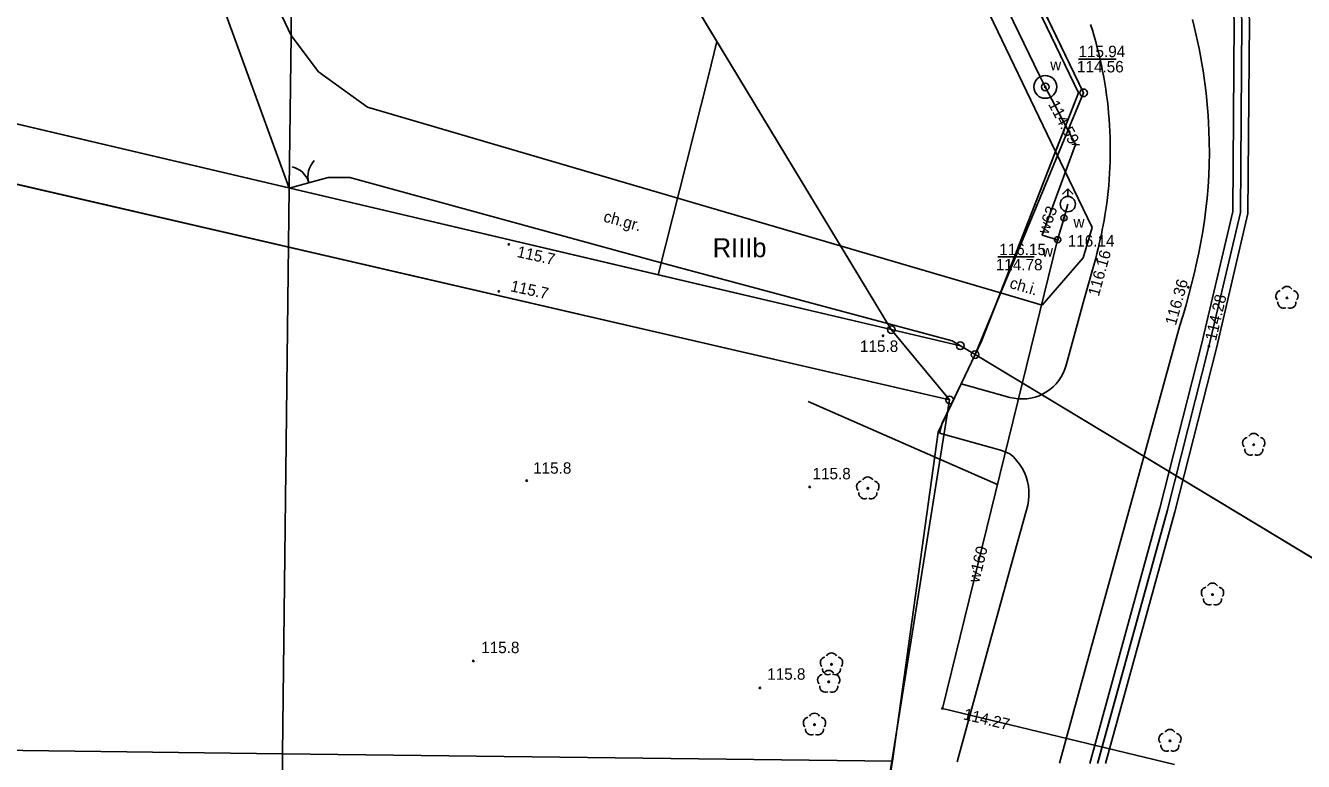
# Model space of a CAD drawing. Extents: x 6424617 to 6425697, y 5665845 to 5667190.
# Drawn here: x 6425294.6 to 6425378.5, y 5666814.1 to 5666862.4 of the extents above; entities that cross this region are included whole.
import ezdxf

# ---------------------------------------------------------------- set-up
doc = ezdxf.new("R2010")
doc.units = 0
for name, color, linetype in [('Warstwa 1', 7, 'Continuous'), ('Warstwa 10', 7, 'Continuous'), ('Warstwa 11', 7, 'Continuous'), ('Warstwa 12', 7, 'Continuous'), ('Warstwa 13', 7, 'Continuous'), ('Warstwa 14', 7, 'Continuous'), ('Warstwa 15', 7, 'Continuous'), ('Warstwa 16', 7, 'Continuous'), ('Warstwa 2', 7, 'Continuous'), ('Warstwa 20', 7, 'Continuous'), ('Warstwa 25', 7, 'Continuous'), ('Warstwa 3', 7, 'Continuous'), ('Warstwa 4', 7, 'Continuous'), ('Warstwa 5', 7, 'Continuous'), ('Warstwa 6', 7, 'Continuous'), ('Warstwa 61', 7, 'Continuous'), ('Warstwa 8', 7, 'Continuous'), ('Warstwa 9', 7, 'Continuous')]:
    doc.layers.add(name, color=color, linetype=linetype)

msp = doc.modelspace()

# ---------------------------------------------------------------- linework, layer by layer
at = {"layer": 'Warstwa 1'}
for p, q in [((6425289.177, 5666945.34), (6425340.017, 5666861.361)), ((6425289.177, 5666945.34), (6425340.017, 5666861.361)), ((6425325.81, 5666937.38), (6425364.08, 5666857.99)), ((6425325.81, 5666937.38), (6425364.08, 5666857.99)), ((6425339.472, 5666859.115), (6425340.017, 5666861.361)), ((6425339.472, 5666859.115), (6425340.017, 5666861.361)), ((6425340.017, 5666861.361), (6425351.457, 5666842.463)), ((6425340.017, 5666861.361), (6425351.457, 5666842.463)), ((6425336.17, 5666846.056), (6425339.472, 5666859.115)), ((6425336.17, 5666846.056), (6425339.472, 5666859.115)), ((6425356.96, 5666840.82), (6425364.08, 5666857.99)), ((6425356.96, 5666840.82), (6425364.08, 5666857.99)), ((6425289.639, 5666856.991), (6425351.457, 5666842.463)), ((6425289.639, 5666856.991), (6425336.17, 5666846.056)), ((6425290.369, 5666852.842), (6425355.292, 5666837.846)), ((6425290.369, 5666852.842), (6425355.292, 5666837.846)), ((6425336.17, 5666846.056), (6425351.457, 5666842.463)), ((6425351.457, 5666842.463), (6425355.292, 5666837.846)), ((6425351.457, 5666842.463), (6425355.995, 5666841.398)), ((6425351.457, 5666842.463), (6425355.292, 5666837.846)), ((6425351.457, 5666842.463), (6425355.995, 5666841.398)), ((6425355.995, 5666841.398), (6425356.96, 5666840.82)), ((6425355.995, 5666841.398), (6425356.96, 5666840.82)), ((6425356.96, 5666840.82), (6425392.62, 5666819.33)), ((6425356.96, 5666840.82), (6425437.407, 5666792.342)), ((6425348.185, 5666793.45), (6425355.292, 5666837.846)), ((6425348.185, 5666793.45), (6425355.292, 5666837.846))]:
    msp.add_line(p, q, dxfattribs=at)
at = {"layer": 'Warstwa 10'}
msp.add_lwpolyline([(6425365.002, 5666813.998), (6425369.58, 5666830.63), (6425372.31, 5666841.36), (6425374.37, 5666850.14), (6425374.47, 5666862.67), (6425373.34, 5666884.86), (6425372.35, 5666897.94), (6425372.09, 5666921.2), (6425370.11, 5666938.36), (6425369.62, 5666940.17), (6425363.11, 5666950.45), (6425345.89, 5666974.19), (6425342.73, 5666979.13), (6425333.68, 5666990.9), (6425313.986, 5667019.515)], dxfattribs=at)
for centre in [(6425364.08, 5666857.99), (6425351.457, 5666842.463), (6425351.457, 5666842.463), (6425355.995, 5666841.398), (6425355.995, 5666841.398), (6425356.96, 5666840.82), (6425356.96, 5666840.82), (6425355.292, 5666837.846)]:
    msp.add_circle(centre, 0.25, dxfattribs=at)
at = {"layer": 'Warstwa 11'}
for centre in [(6425377.426, 5666844.539), (6425375.252, 5666834.905), (6425349.922, 5666832.044), (6425372.543, 5666825.081), (6425347.539, 5666820.501), (6425347.359, 5666819.355), (6425346.425, 5666816.548), (6425369.749, 5666815.488)]:
    msp.add_circle(centre, 0.05, dxfattribs=at)
for centre, start, end in [((6425377.426, 5666844.914), 30.14713, 149.85287), ((6425377.069, 5666844.655), 102.14713, 221.85287), ((6425377.783, 5666844.655), 318.14713, 77.85287), ((6425377.206, 5666844.236), 174.14713, 293.85287), ((6425377.646, 5666844.236), 246.14713, 5.85287), ((6425374.895, 5666835.021), 102.14713, 221.85287), ((6425375.252, 5666835.28), 30.14713, 149.85287), ((6425375.609, 5666835.021), 318.14713, 77.85287), ((6425375.032, 5666834.602), 174.14713, 293.85287), ((6425375.472, 5666834.602), 246.14713, 5.85287), ((6425349.922, 5666832.419), 30.14713, 149.85287), ((6425349.565, 5666832.16), 102.14713, 221.85287), ((6425349.702, 5666831.741), 174.14713, 293.85287), ((6425350.142, 5666831.741), 246.14713, 5.85287), ((6425350.279, 5666832.16), 318.14713, 77.85287), ((6425372.186, 5666825.197), 102.14713, 221.85287), ((6425372.543, 5666825.456), 30.14713, 149.85287), ((6425372.9, 5666825.197), 318.14713, 77.85287), ((6425372.323, 5666824.778), 174.14713, 293.85287), ((6425372.763, 5666824.778), 246.14713, 5.85287), ((6425347.182, 5666820.617), 102.14713, 221.85287), ((6425347.539, 5666820.876), 30.14713, 149.85287), ((6425347.896, 5666820.617), 318.14713, 77.85287), ((6425347.319, 5666820.198), 174.14713, 293.85287), ((6425347.359, 5666819.73), 30.14713, 149.85287), ((6425347.759, 5666820.198), 246.14713, 5.85287), ((6425347.002, 5666819.471), 102.14713, 221.85287), ((6425347.716, 5666819.471), 318.14713, 77.85287), ((6425347.139, 5666819.052), 174.14713, 293.85287), ((6425347.579, 5666819.052), 246.14713, 5.85287), ((6425346.068, 5666816.664), 102.14713, 221.85287), ((6425346.425, 5666816.923), 30.14713, 149.85287), ((6425346.782, 5666816.664), 318.14713, 77.85287), ((6425346.205, 5666816.245), 174.14713, 293.85287), ((6425346.645, 5666816.245), 246.14713, 5.85287), ((6425369.392, 5666815.604), 102.14713, 221.85287), ((6425369.749, 5666815.863), 30.14713, 149.85287), ((6425370.106, 5666815.604), 318.14713, 77.85287), ((6425369.529, 5666815.185), 174.14713, 293.85287), ((6425369.969, 5666815.185), 246.14713, 5.85287)]:
    msp.add_arc(centre, 0.375, start, end, dxfattribs=at)
at = {"layer": 'Warstwa 12'}
for points in [[(6425313.249, 5666958.616), (6425313.289, 5666958.53), (6425325.737, 5666932.606), (6425333.614, 5666916.67), (6425342.544, 5666898.009), (6425352.162, 5666877.811), (6425353.034, 5666875.987), (6425361.192, 5666859.133), (6425361.57, 5666858.38), (6425363.56, 5666854.6)], [(6425362.38, 5666848.35), (6425361.37, 5666848.66), (6425363.56, 5666854.6)], [(6425362.381, 5666848.353), (6425362.8, 5666849.79), (6425363.05, 5666850.69)], [(6425370.039, 5666813.938), (6425354.82, 5666817.61), (6425362.38, 5666848.35), (6425362.381, 5666848.353)]]:
    msp.add_lwpolyline(points, dxfattribs=at)
at = {"layer": 'Warstwa 13'}
for centre in [(6425326.364, 5666848.045), (6425325.709, 5666844.961), (6425350.928, 5666842.055), (6425327.536, 5666832.56), (6425346.107, 5666832.137), (6425324.035, 5666820.729), (6425342.845, 5666818.96)]:
    msp.add_circle(centre, 0.045, dxfattribs=at)
at = {"layer": 'Warstwa 14'}
for p, q in [((6425366.217, 5666860.206), (6425363.749, 5666860.206)), ((6425360.832, 5666847.222), (6425358.448, 5666847.222))]:
    msp.add_line(p, q, dxfattribs=at)
for centre in [(6425361.57, 5666858.38), (6425363.56, 5666854.6), (6425362.8, 5666849.79), (6425362.38, 5666848.35), (6425372.31, 5666841.36), (6425354.82, 5666817.61)]:
    msp.add_circle(centre, 0.045, dxfattribs=at)
at = {"layer": 'Warstwa 16'}
msp.add_circle((6425361.57, 5666858.38), 0.75, dxfattribs=at)
at = {"layer": 'Warstwa 2'}
for points in [[(6425313.841, 5667007.532), (6425316.22, 5667006.94), (6425339.85, 5666976.82), (6425352.5, 5666950.5), (6425325.41, 5666937.52), (6425363.75, 5666857.98), (6425357.38, 5666841.7), (6425354.53, 5666835.73), (6425351.541, 5666814.161)], [(6425351.541, 5666814.161), (6425346.19, 5666783.6), (6425359.15, 5666739.31), (6425316.945, 5666564.569)]]:
    msp.add_lwpolyline(points, dxfattribs=at)
at = {"layer": 'Warstwa 20'}
msp.add_line((6425363.809, 5666854.578), (6425363.311, 5666854.622), dxfattribs=at)
at = {"layer": 'Warstwa 25'}
for centre in [(6425364.948, 5666847.065), (6425370.957, 5666845.236)]:
    msp.add_circle(centre, 0.045, dxfattribs=at)
at = {"layer": 'Warstwa 3'}
msp.add_lwpolyline([(6425314.511, 5666852.444), (6425311.957, 5666851.747)], dxfattribs=at)
for centre, start, end in [((6425311.792, 5666851.683), 15.95687, 75.95687), ((6425314.676, 5666852.507), 135.95687, 195.95687)]:
    msp.add_arc(centre, 1.5, start, end, dxfattribs=at)
at = {"layer": 'Warstwa 4'}
for points in [[(6425362.696, 5666851.336), (6425363.05, 5666851.69)], [(6425363.404, 5666851.336), (6425363.05, 5666851.69)], [(6425363.05, 5666851.19), (6425363.05, 5666851.69)], [(6425358.485, 5666832.271), (6425346.016, 5666837.741)]]:
    msp.add_lwpolyline(points, dxfattribs=at)
for centre, radius in [((6425361.57, 5666858.38), 0.25), ((6425363.05, 5666850.69), 0.5), ((6425362.8, 5666849.79), 0.2), ((6425362.38, 5666848.35), 0.2)]:
    msp.add_circle(centre, radius, dxfattribs=at)
at = {"layer": 'Warstwa 6'}
for points in [[(6425269.791, 5667072.474), (6425266.76, 5667059.81), (6425286.52, 5667014.65), (6425316.39, 5667007.21), (6425340.11, 5666976.98), (6425352.9, 5666950.36), (6425325.81, 5666937.38), (6425364.08, 5666857.99), (6425356.96, 5666840.82), (6425355.995, 5666841.398), (6425351.457, 5666842.463), (6425289.177, 5666945.34), (6425291.964, 5666957.537), (6425280.019, 5666960.482), (6425262.733, 5666989.032), (6425234.439, 5667063.338), (6425238.455, 5667079.5)], [(6425493.084, 5667022.41), (6425437.407, 5666792.342), (6425392.62, 5666819.33), (6425356.96, 5666840.82), (6425364.08, 5666857.99), (6425325.81, 5666937.38), (6425352.9, 5666950.36), (6425340.11, 5666976.98), (6425316.39, 5667007.21), (6425286.52, 5667014.65), (6425266.76, 5667059.81), (6425269.791, 5667072.474)], [(6425290.369, 5666852.842), (6425355.292, 5666837.846), (6425351.457, 5666842.463), (6425289.639, 5666856.991)], [(6425244.275, 5666264.977), (6425279.037, 5666410.906), (6425312.219, 5666546.795), (6425313.029, 5666550.146), (6425358.794, 5666739.45), (6425345.837, 5666783.728), (6425348.185, 5666793.45), (6425355.292, 5666837.846), (6425351.457, 5666842.463), (6425355.995, 5666841.398), (6425356.96, 5666840.82), (6425392.62, 5666819.33), (6425392.36, 5666816.84), (6425379.44, 5666763.67), (6425335.03, 5666581.17), (6425333.09, 5666581.65), (6425294.11, 5666422.45), (6425272.8, 5666335.34)]]:
    msp.add_lwpolyline(points, dxfattribs=at)
for points in [[(6425050.777, 5666937.571), (6425044.76, 5666913.763), (6425086.982, 5666903.842), (6425106.359, 5666899.348), (6425147.775, 5666889.687), (6425182.111, 5666881.731), (6425270.211, 5666861.456), (6425271.789, 5666861.227), (6425279.327, 5666859.415), (6425289.639, 5666856.991), (6425351.457, 5666842.463), (6425289.177, 5666945.34), (6425275.048, 5666883.498)], [(6425358.794, 5666739.45), (6425345.837, 5666783.728), (6425348.185, 5666793.45), (6425355.292, 5666837.846), (6425290.369, 5666852.842), (6425257.3, 5666717.295), (6425256.529, 5666713.915), (6425237.206, 5666634.214), (6425213.474, 5666536.345), (6425279.567, 5666529.498), (6425296.119, 5666527.878), (6425306.817, 5666551.711), (6425313.029, 5666550.146)]]:
    msp.add_lwpolyline(points, close=True, dxfattribs=at)
at = {"layer": 'Warstwa 61'}
msp.add_lwpolyline([(6425313.986, 5667019.516), (6425314.387, 5667018.932), (6425333.673, 5666990.911), (6425333.688, 5666990.89), (6425342.73, 5666979.13), (6425345.89, 5666974.19), (6425363.11, 5666950.45), (6425369.62, 5666940.17), (6425370.11, 5666938.36), (6425372.09, 5666921.2), (6425372.35, 5666897.94), (6425373.34, 5666884.86), (6425374.47, 5666862.67), (6425374.37, 5666850.14), (6425372.31, 5666841.36), (6425369.581, 5666830.635), (6425369.579, 5666830.625), (6425365.037, 5666814.125), (6425365.002, 5666813.999)], dxfattribs=at)
at = {"layer": 'Warstwa 8'}
for p, q in [((6425371.22, 5666862.808), (6425371.343, 5666862.331)), ((6425364.539, 5666862.473), (6425364.658, 5666862.095)), ((6425364.658, 5666862.095), (6425364.772, 5666861.715)), ((6425371.343, 5666862.331), (6425371.459, 5666861.853)), ((6425364.772, 5666861.715), (6425364.881, 5666861.334)), ((6425364.881, 5666861.334), (6425364.984, 5666860.952)), ((6425371.459, 5666861.853), (6425371.568, 5666861.373)), ((6425371.568, 5666861.373), (6425371.67, 5666860.892)), ((6425364.984, 5666860.952), (6425365.082, 5666860.567)), ((6425365.082, 5666860.567), (6425365.171, 5666860.18)), ((6425371.67, 5666860.892), (6425371.764, 5666860.409)), ((6425371.764, 5666860.409), (6425371.852, 5666859.925)), ((6425365.171, 5666860.18), (6425365.255, 5666859.791)), ((6425365.255, 5666859.791), (6425365.333, 5666859.402)), ((6425371.852, 5666859.925), (6425371.931, 5666859.439)), ((6425371.931, 5666859.439), (6425372.004, 5666858.951)), ((6425365.333, 5666859.402), (6425365.406, 5666859.011)), ((6425365.406, 5666859.011), (6425365.473, 5666858.62)), ((6425365.473, 5666858.62), (6425365.535, 5666858.227)), ((6425372.004, 5666858.951), (6425372.069, 5666858.462)), ((6425365.535, 5666858.227), (6425365.592, 5666857.834)), ((6425365.592, 5666857.834), (6425365.642, 5666857.44)), ((6425372.069, 5666858.462), (6425372.127, 5666857.973)), ((6425372.127, 5666857.973), (6425372.178, 5666857.482)), ((6425365.642, 5666857.44), (6425365.688, 5666857.045)), ((6425365.688, 5666857.045), (6425365.727, 5666856.651)), ((6425372.178, 5666857.482), (6425372.223, 5666856.991)), ((6425372.223, 5666856.991), (6425372.26, 5666856.5)), ((6425365.727, 5666856.651), (6425365.76, 5666856.257)), ((6425365.76, 5666856.257), (6425365.787, 5666855.862)), ((6425372.26, 5666856.5), (6425372.29, 5666856.008)), ((6425365.787, 5666855.862), (6425365.808, 5666855.468)), ((6425365.808, 5666855.468), (6425365.823, 5666855.072)), ((6425372.29, 5666856.008), (6425372.313, 5666855.515)), ((6425372.313, 5666855.515), (6425372.332, 5666854.776)), ((6425365.823, 5666855.072), (6425365.832, 5666854.677)), ((6425365.832, 5666854.677), (6425365.835, 5666854.282)), ((6425372.332, 5666854.776), (6425372.336, 5666854.038)), ((6425365.824, 5666853.491), (6425365.832, 5666853.886)), ((6425365.832, 5666853.886), (6425365.835, 5666854.282)), ((6425372.323, 5666853.299), (6425372.336, 5666854.038)), ((6425365.789, 5666852.697), (6425365.81, 5666853.094)), ((6425365.81, 5666853.094), (6425365.824, 5666853.491)), ((6425372.293, 5666852.561), (6425372.323, 5666853.299)), ((6425365.692, 5666851.51), (6425365.73, 5666851.905)), ((6425365.73, 5666851.905), (6425365.763, 5666852.301)), ((6425365.763, 5666852.301), (6425365.789, 5666852.697)), ((6425372.248, 5666851.823), (6425372.293, 5666852.561)), ((6425365.598, 5666850.721), (6425365.648, 5666851.115)), ((6425365.648, 5666851.115), (6425365.692, 5666851.51)), ((6425372.108, 5666850.353), (6425372.186, 5666851.087)), ((6425372.186, 5666851.087), (6425372.248, 5666851.823)), ((6425365.48, 5666849.936), (6425365.542, 5666850.328)), ((6425365.542, 5666850.328), (6425365.598, 5666850.721)), ((6425372.013, 5666849.62), (6425372.108, 5666850.353)), ((6425365.371, 5666849.314), (6425365.427, 5666849.625)), ((6425365.427, 5666849.625), (6425365.48, 5666849.936)), ((6425371.903, 5666848.89), (6425372.013, 5666849.62)), ((6425365.181, 5666848.384), (6425365.248, 5666848.693)), ((6425365.248, 5666848.693), (6425365.311, 5666849.003)), ((6425365.311, 5666849.003), (6425365.371, 5666849.314)), ((6425371.777, 5666848.195), (6425371.903, 5666848.89)), ((6425364.96, 5666847.462), (6425365.037, 5666847.769)), ((6425365.037, 5666847.769), (6425365.111, 5666848.076)), ((6425365.111, 5666848.076), (6425365.181, 5666848.384)), ((6425371.641, 5666847.503), (6425371.777, 5666848.195)), ((6425364.13, 5666844.449), (6425364.879, 5666847.156)), ((6425364.879, 5666847.156), (6425364.96, 5666847.462)), ((6425371.495, 5666846.813), (6425371.641, 5666847.503)), ((6425371.171, 5666845.439), (6425371.338, 5666846.125)), ((6425371.338, 5666846.125), (6425371.495, 5666846.813)), ((6425370.994, 5666844.756), (6425371.171, 5666845.439)), ((6425362.942, 5666840.119), (6425364.13, 5666844.449)), ((6425370.806, 5666844.076), (6425370.994, 5666844.756)), ((6425370.609, 5666843.399), (6425370.806, 5666844.076)), ((6425367.746, 5666833.08), (6425370.401, 5666842.725)), ((6425370.401, 5666842.725), (6425370.609, 5666843.399)), ((6425362.459, 5666839.128), (6425362.613, 5666839.358)), ((6425362.613, 5666839.358), (6425362.746, 5666839.601)), ((6425362.746, 5666839.601), (6425362.856, 5666839.856)), ((6425362.856, 5666839.856), (6425362.942, 5666840.119)), ((6425354.812, 5666836.32), (6425356.043, 5666838.899)), ((6425356.043, 5666838.899), (6425359.253, 5666838.015)), ((6425361.651, 5666838.377), (6425361.878, 5666838.536)), ((6425361.878, 5666838.536), (6425362.089, 5666838.715)), ((6425362.089, 5666838.715), (6425362.283, 5666838.913)), ((6425362.283, 5666838.913), (6425362.459, 5666839.128)), ((6425359.253, 5666838.015), (6425359.524, 5666837.955)), ((6425359.524, 5666837.955), (6425359.799, 5666837.92)), ((6425359.799, 5666837.92), (6425360.076, 5666837.91)), ((6425360.076, 5666837.91), (6425360.352, 5666837.926)), ((6425360.352, 5666837.926), (6425360.626, 5666837.968)), ((6425360.626, 5666837.968), (6425360.895, 5666838.034)), ((6425360.895, 5666838.034), (6425361.157, 5666838.125)), ((6425361.157, 5666838.125), (6425361.41, 5666838.24)), ((6425361.41, 5666838.24), (6425361.651, 5666838.377)), ((6425354.629, 5666835.658), (6425354.812, 5666836.32)), ((6425354.629, 5666835.658), (6425358.321, 5666834.641)), ((6425358.321, 5666834.641), (6425358.634, 5666834.556)), ((6425358.634, 5666834.556), (6425358.94, 5666834.447)), ((6425358.94, 5666834.447), (6425359.236, 5666834.314)), ((6425359.236, 5666834.314), (6425359.473, 5666834.109)), ((6425359.473, 5666834.109), (6425359.689, 5666833.882)), ((6425359.689, 5666833.882), (6425359.883, 5666833.636)), ((6425359.883, 5666833.636), (6425360.053, 5666833.373)), ((6425360.053, 5666833.373), (6425360.197, 5666833.095)), ((6425360.197, 5666833.095), (6425360.315, 5666832.805)), ((6425360.315, 5666832.805), (6425360.404, 5666832.504)), ((6425364.557, 5666821.514), (6425367.746, 5666833.08)), ((6425360.404, 5666832.504), (6425360.465, 5666832.197)), ((6425360.465, 5666832.197), (6425360.497, 5666831.885)), ((6425360.497, 5666831.885), (6425360.5, 5666831.572)), ((6425359.356, 5666827.09), (6425360.416, 5666830.952)), ((6425360.416, 5666830.952), (6425360.472, 5666831.26)), ((6425360.472, 5666831.26), (6425360.5, 5666831.572)), ((6425357.761, 5666821.306), (6425359.356, 5666827.09)), ((6425355.783, 5666814.11), (6425357.761, 5666821.306)), ((6425362.497, 5666814.029), (6425364.557, 5666821.514))]:
    msp.add_line(p, q, dxfattribs=at)
for points in [[(6425371.59, 5666921.168), (6425371.85, 5666897.918), (6425372.841, 5666884.828), (6425373.97, 5666862.659), (6425373.87, 5666850.2), (6425371.824, 5666841.479), (6425369.097, 5666830.758), (6425364.485, 5666814.005)], [(6425365.519, 5666813.992), (6425370.063, 5666830.502), (6425372.796, 5666841.241), (6425374.87, 5666850.08), (6425374.97, 5666862.681), (6425373.839, 5666884.892), (6425372.85, 5666897.962), (6425372.59, 5666921.232)]]:
    msp.add_lwpolyline(points, dxfattribs=at)
at = {"layer": 'Warstwa 9'}
for p, q in [((6425312.078, 5666861.746), (6425313.213, 5666955.639)), ((6425312.078, 5666861.746), (6425313.213, 5666955.639)), ((6425353.091, 5666880.093), (6425363.75, 5666857.98)), ((6425350.774, 5666877.983), (6425362.246, 5666854.136)), ((6425305.485, 5666875.702), (6425312.078, 5666861.746)), ((6425357.936, 5666870.041), (6425363.75, 5666857.98)), ((6425306.588, 5666866.44), (6425311.957, 5666851.747)), ((6425311.957, 5666851.747), (6425312.078, 5666861.746)), ((6425311.957, 5666851.747), (6425312.078, 5666861.746)), ((6425311.957, 5666851.747), (6425312.078, 5666861.746)), ((6425311.957, 5666851.747), (6425312.078, 5666861.746)), ((6425312.078, 5666861.746), (6425313.882, 5666859.357)), ((6425313.882, 5666859.357), (6425317.089, 5666857.048)), ((6425362.246, 5666854.136), (6425363.75, 5666857.98)), ((6425362.246, 5666854.136), (6425363.75, 5666857.98)), ((6425317.089, 5666857.048), (6425358.622, 5666844.873)), ((6425358.622, 5666844.873), (6425362.246, 5666854.136)), ((6425358.622, 5666844.873), (6425362.246, 5666854.136)), ((6425362.246, 5666854.136), (6425364.644, 5666849.15)), ((6425311.957, 5666851.747), (6425314.511, 5666852.444)), ((6425314.511, 5666852.444), (6425315.936, 5666852.427)), ((6425315.936, 5666852.427), (6425335.719, 5666847.016)), ((6425311.509, 5666814.644), (6425311.957, 5666851.747)), ((6425311.509, 5666814.644), (6425311.957, 5666851.747)), ((6425364.06, 5666847.168), (6425364.644, 5666849.15)), ((6425335.719, 5666847.016), (6425355.448, 5666841.728)), ((6425361.369, 5666844.068), (6425364.06, 5666847.168)), ((6425357.38, 5666841.7), (6425358.622, 5666844.873)), ((6425357.38, 5666841.7), (6425358.622, 5666844.873)), ((6425358.622, 5666844.873), (6425361.369, 5666844.068)), ((6425355.448, 5666841.728), (6425355.995, 5666841.398)), ((6425355.995, 5666841.398), (6425356.96, 5666840.82)), ((6425356.96, 5666840.82), (6425357.38, 5666841.7)), ((6425356.96, 5666840.82), (6425357.38, 5666841.7)), ((6425356.043, 5666838.899), (6425356.96, 5666840.82)), ((6425354.53, 5666835.73), (6425356.043, 5666838.899)), ((6425351.541, 5666814.161), (6425354.53, 5666835.73)), ((6425036.138, 5666817.971), (6425311.509, 5666814.644)), ((6425279.659, 5666815.029), (6425311.509, 5666814.644)), ((6425308.494, 5666564.671), (6425311.509, 5666814.644)), ((6425308.494, 5666564.671), (6425311.509, 5666814.644)), ((6425311.509, 5666814.644), (6425351.541, 5666814.161)), ((6425311.509, 5666814.644), (6425351.541, 5666814.161)), ((6425346.19, 5666783.6), (6425351.541, 5666814.161))]:
    msp.add_line(p, q, dxfattribs=at)

# ---------------------------------------------------------------- texts
at = {"layer": 'Warstwa 13'}
for s, rotation, p in [('w63', 69.76334, (6425361.742, 5666848.662)), ('115.7', 347.46453, (6425326.852, 5666847.23)), ('115.7', 347.68798, (6425326.428, 5666844.983)), ('w160', 76.18047, (6425357.224, 5666825.818))]:
    msp.add_text(s, height=0.75, rotation=rotation, dxfattribs=at).set_placement(p)
for p in [(6425349.409, 5666840.997), (6425327.958, 5666833.007), (6425346.293, 5666832.637), (6425324.55, 5666821.237), (6425343.32, 5666819.493)]:
    msp.add_text('115.8', height=0.75, dxfattribs=at).set_placement(p)
at = {"layer": 'Warstwa 14'}
for s, p in [('114.56', (6425363.649, 5666859.331)), ('114.78', (6425358.323, 5666846.346))]:
    msp.add_text(s, height=0.75, dxfattribs=at).set_placement(p)
for s, rotation, p in [('114.59', 297.76617, (6425361.742, 5666857.25)), ('114.28', 76.79353, (6425372.77, 5666841.68)), ('114.27', 346.4332, (6425356.144, 5666816.904))]:
    msp.add_text(s, height=0.75, rotation=rotation, dxfattribs=at).set_placement(p)
at = {"layer": 'Warstwa 15'}
for s, p in [('115.94', (6425363.749, 5666860.331)), ('116.14', (6425363.042, 5666847.906)), ('116.15', (6425358.547, 5666847.346))]:
    msp.add_text(s, height=0.75, dxfattribs=at).set_placement(p)
at = {"layer": 'Warstwa 2'}
msp.add_text('RIIIb', height=1.25, dxfattribs=at).set_placement((6425339.744, 5666847.206))
at = {"layer": 'Warstwa 25'}
for s, p in [('116.16', (6425365.078, 5666844.597)), ('116.36', (6425370.135, 5666842.691))]:
    msp.add_text(s, height=0.75, rotation=74.53608, dxfattribs=at).set_placement(p)
at = {"layer": 'Warstwa 5'}
for p in [(6425361.894, 5666859.469), (6425363.418, 5666849.137), (6425361.354, 5666847.243)]:
    msp.add_text('w', height=0.75, dxfattribs=at).set_placement(p)
at = {"layer": 'Warstwa 9'}
for s, rotation, p in [('ch.gr.', 344.70287, (6425332.522, 5666849.557)), ('ch.i.', 343.66009, (6425359.177, 5666845.203))]:
    msp.add_text(s, height=0.75, rotation=rotation, dxfattribs=at).set_placement(p)

doc.saveas('drawing.dxf')
